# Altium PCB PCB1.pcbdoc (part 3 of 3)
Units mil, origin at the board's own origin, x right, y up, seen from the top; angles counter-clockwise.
Board outline 4706 x 2788 mil, 2 copper layers (Top Layer, Bottom Layer); 153 components, 206 nets, 1095 pads, 513 vias.
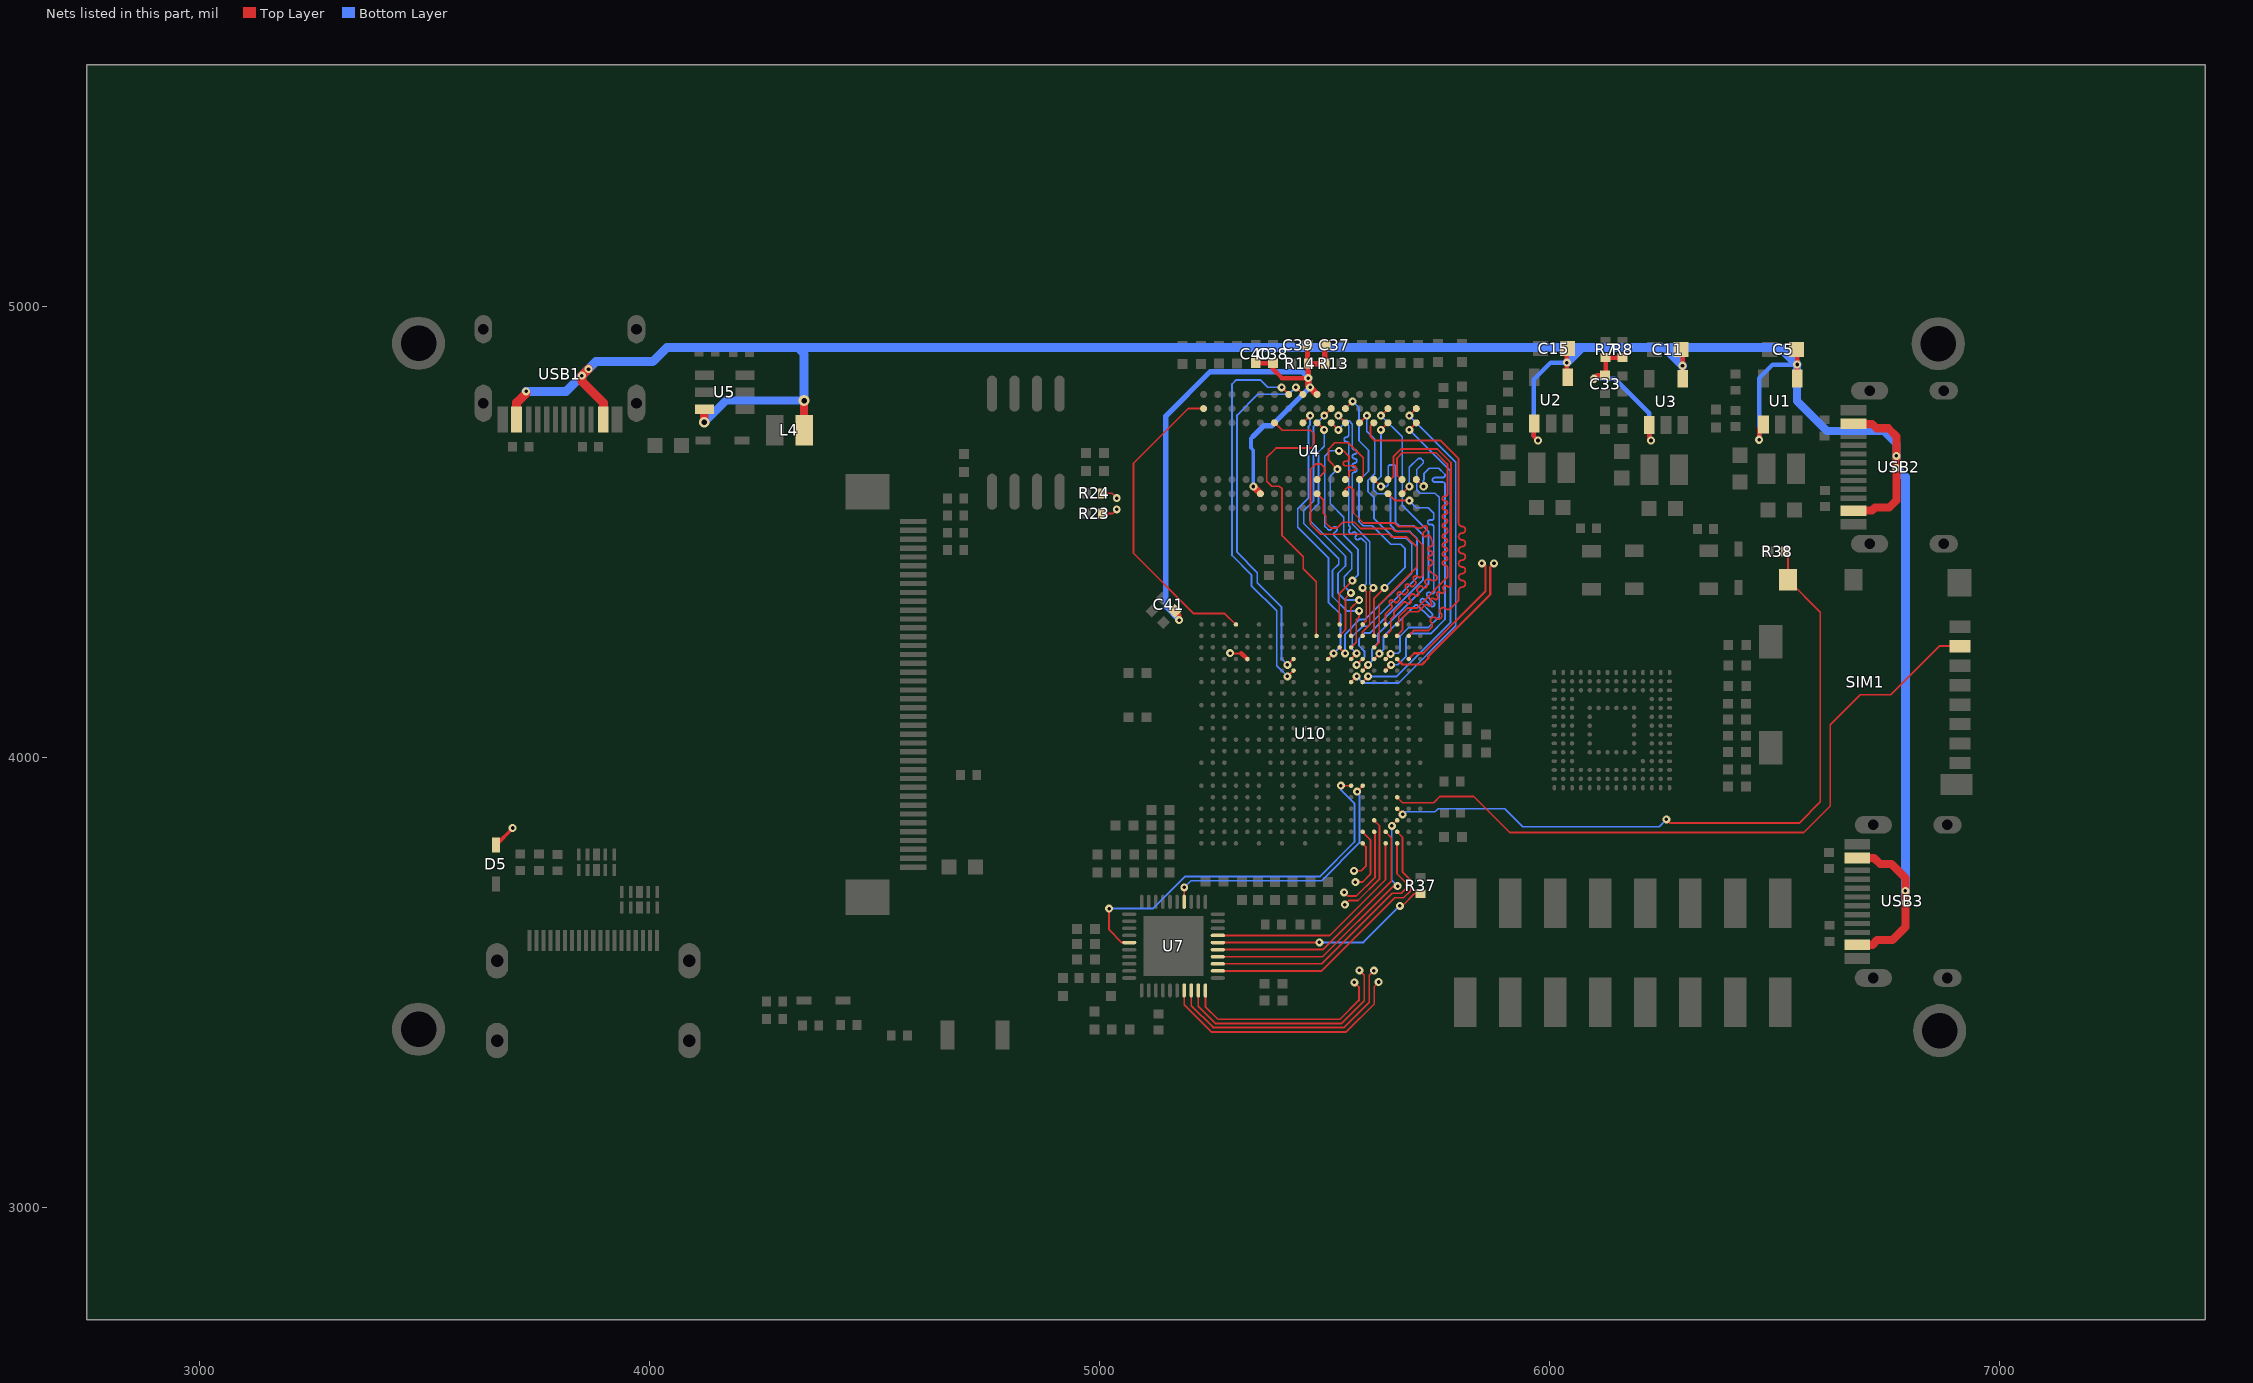
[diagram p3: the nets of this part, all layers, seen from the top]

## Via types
v1: diameter 17.7, hole 7.9, Top Layer to Bottom Layer, 233 vias
v2: diameter 17.72, hole 7.87, Top Layer to Bottom Layer, 140 vias
v3: diameter 17.7, hole 8, Top Layer to Bottom Layer, 88 vias
v4: diameter 18, hole 8, Top Layer to Bottom Layer, 38 vias
v5: diameter 24, hole 15, Top Layer to Bottom Layer, 8 vias
v6: diameter 24, hole 12, Top Layer to Bottom Layer, 6 vias

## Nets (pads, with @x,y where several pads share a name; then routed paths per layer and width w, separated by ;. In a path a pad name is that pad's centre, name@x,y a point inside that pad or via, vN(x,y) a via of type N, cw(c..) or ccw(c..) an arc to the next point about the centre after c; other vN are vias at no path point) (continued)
SDC0_D3: SIM1.2 U10.E3 | length 1571.6
  Top Layer w4: U10.E3@5660.56,3910.73 5672.8,3898.5 5742,3898.5 5756,3912.5 5831,3912.5 5911,3832.5 6564,3832.5 6623,3891.5 6623,4071.5 6690,4138.5 6757,4138.5 6865.2,4246.7 SIM1.2@6911.1,4246.7
SDC0_DET: R38.2 SIM1.12 U10.D3 | length 1585.4
  Top Layer w4: U10.D3@5660.56,3885.14 v1(5673,3872.71) v1@5673,3872.5 ; v1(6259,3861.5) 6267,3853.5 6554,3853.5 6601,3900.5 6601,4322 SIM1.12@6529.2,4393.8 6529.2,4450.31 R38.2@6523,4456.5
  Bottom Layer w4: v1(5673,3872.71) 5678.79,3878.5 5745,3878.5 5752,3885.5 5900,3885.5 5940,3845.5 6243,3845.5 v1(6259,3861.5)
SDC1_CLK: R37.2 U7.16 | length 495.4
  Top Layer w4: U7.16@5262.56,3588.07 5262.99,3588.5 v1(5488,3588.5) ; v1(5667,3669.5) 5670,3672.5 5675,3672.5 5699,3696.5 R37.2@5713,3696.5
  Bottom Layer w4: v1(5488,3588.5) 5586,3588.5 v1(5667,3669.5)
SDC1_CMD: U7.12 U10.B3 | length 645.4
  Top Layer w4: U7.12@5262.56,3525.08 5493.57,3525.08 5656,3687.5 5675,3687.5 5691,3703.5 5691,3726.5 5673,3744.5 5673,3821.53 U10.B3@5660.56,3833.96
SDC1_D0: U7.13 U10.A3 | length 595.4
  Top Layer w4: U7.13@5262.56,3540.83 5493.32,3540.83 5650,3697.5 5670,3697.5 5680,3707.5 5680,3721.5 5660.56,3740.94 U10.A3@5660.56,3808.37
SDC1_D1: U7.14 U10.C3 | length 620.7
  Top Layer w4: U7.14@5262.56,3556.58 5495.07,3556.58 5651,3712.5 5661,3712.5 v1(5662,3713.5) ; v1(5649,3847.5) 5649,3847.99 U10.C3@5660.56,3859.55
  Bottom Layer w4: v1(5649,3847.5) 5649,3726.5 v1(5662,3713.5)
SDC1_D2: U7.17 U10.A4 | length 504.5
  Top Layer w4: U7.17@5262.56,3603.82 5511.31,3603.82 5634.97,3727.47 U10.A4@5634.97,3808.37
SDC1_D3: U7.15 U10.B4 | length 563.3
  Top Layer w4: U7.15@5262.56,3572.33 5495.82,3572.33 5647.76,3724.26 5647.76,3794.26 5648,3794.5 5648,3820.94 U10.B4@5634.97,3833.96
SDQ0: U4.H3 U10.W7 | length 578.3
  Top Layer w4: U4.H3@5483.12,4742.74 v2(5498.87,4727) ; U10.W7@5558.01,4268.98 5558.01,4330.66 v2(5576.24,4348.89)
  Bottom Layer w4: v2(5498.87,4727) 5498.87,4690.52 5486.24,4677.89 5486.24,4562.89 5467.24,4543.89 5467.24,4524.89 5546.24,4445.89 5546.24,4424.89 5529.24,4407.89 5529.24,4364.89 5545.24,4348.89 v2(5576.24,4348.89)
SDQ1: U4.G2 U10.V7 | length 642.4
  Top Layer w4: v2(5499,4758.63) U4.G2@5514.74,4774.37 ; U10.V7@5558.01,4243.39 5570.24,4255.62 5570.24,4304.89 5576.24,4310.89 v2(5576.24,4324.89)
  Bottom Layer w4: v2(5499,4758.63) 5475.24,4734.87 5475.24,4568.89 5453.24,4546.89 5453.24,4518.89 5531.24,4440.89 5531.24,4428.89 5517.24,4414.89 5517.24,4356.89 5549.24,4324.89 v2(5576.24,4324.89)
SDQ2: U4.F7 U10.W8 | length 635.8
  Top Layer w4: v2(5531.7,4680.46) 5541.7,4680.46 5553.7,4668.46 5553.7,4662.2 cw(c5548.7,4662.2) 5548.7,4657.2 5546.18,4657.2 ccw(c5546.18,4652.2) 5541.18,4652.2 ccw(c5546.18,4652.2) 5546.18,4647.2 5564.5,4647.2 cw(c5564.5,4642.2) 5569.5,4642.2 cw(c5564.5,4642.2) 5564.5,4637.2 5558.7,4637.2 ccw(c5558.7,4632.2) 5553.7,4632.2 5553.7,4624.36 U4.F7@5546,4616.65 ; U10.W8@5532.42,4268.98 5546.24,4282.8 5546.24,4352.89 v2(5558.24,4364.89)
  Bottom Layer w4: v2(5531.7,4680.46) 5511.7,4680.46 5499.89,4668.64 5499.89,4513.25 5507.47,4505.67 ccw(c5511.01,4509.2) 5514.54,4505.67 5519.27,4510.39 cw(c5522.8,4506.86) 5526.34,4510.39 cw(c5522.8,4506.86) 5526.34,4503.32 5521.61,4498.6 ccw(c5525.15,4495.06) 5521.61,4491.53 5560.24,4452.89 5560.24,4417.89 5543.24,4400.89 5543.24,4379.89 v2(5558.24,4364.89)
  other v2: 5558.24,4364.89 5558.24,4364.89
SDQ3: U4.E3 U10.V8 | length 706.3
  Top Layer w4: U10.V8@5532.42,4243.39 v2(5545.22,4230.6) ; U4.E3@5577.74,4742.87 v2(5593.49,4758.62)
  Bottom Layer w4: v2(5545.22,4230.6) 5545.22,4272.87 5578.24,4305.89 5590.24,4305.89 5693.24,4408.89 5693.24,4473.89 5680.24,4486.89 5653.24,4486.89 5609.24,4530.89 5609.24,4576.89 5596.24,4589.89 5596.24,4614.89 5611.24,4629.89 5611.24,4705.89 5593.49,4723.65 v2(5593.49,4758.62)
SDQ4: U4.F8 U10.W4 | length 670
  Top Layer w4: U4.F8@5546,4585.15 5546,4594.65 5551.24,4599.89 5558.24,4599.89 5563.87,4594.27 5563.87,4542.27 5586.24,4519.89 5655.24,4519.89 5662.99,4512.15 5695.5,4512.15 cw(c5695.5,4495.14) 5703.5,4510.15 ccw(c5709.78,4521.94) 5719.23,4512.5 cw(c5722.77,4508.96) 5726.3,4512.5 cw(c5722.77,4508.96) 5726.3,4505.42 5719.23,4498.35 ccw(c5722.77,4494.82) 5719.23,4491.28 ccw(c5722.77,4494.82) 5726.3,4491.28 cw(c5729.84,4487.75) 5733.37,4491.28 cw(c5708.75,4472.86) 5739.5,4472.86 cw(c5734.5,4472.86) 5734.5,4467.86 ccw(c5734.5,4462.86) 5729.5,4462.86 ccw(c5734.5,4462.86) 5734.5,4457.86 cw(c5734.5,4452.86) 5739.5,4452.86 cw(c5734.5,4452.86) 5734.5,4447.86 ccw(c5734.5,4442.86) 5729.5,4442.86 ccw(c5734.5,4442.86) 5734.5,4437.86 cw(c5734.5,4432.86) 5739.5,4432.86 cw(c5732.87,4431.86) 5735,4425.5 ccw(c5737.03,4419.44) 5732,4415.5 ccw(c5761.5,4438.64) 5746,4404.5 cw(c5743.4,4398.78) 5748,4394.5 cw(c5741.45,4400.6) 5736,4393.5 ccw(c5730.48,4386.31) 5724.07,4392.72 ccw(c5727.6,4389.18) 5724.07,4385.65 5725.5,4384.22 cw(c5721.96,4380.69) 5725.5,4377.15 cw(c5721.96,4380.69) 5718.43,4377.15 5717,4378.58 ccw(c5713.46,4375.04) 5709.93,4378.58 5706.39,4375.04 ccw(c5709.93,4371.51) 5706.39,4367.97 5707.82,4366.54 cw(c5704.28,4363.01) 5707.82,4359.47 cw(c5704.28,4363.01) 5700.75,4359.47 5699.32,4360.9 ccw(c5695.78,4357.36) 5692.25,4360.9 5688.71,4357.36 ccw(c5692.25,4353.83) 5688.71,4350.29 5690.14,4348.87 cw(c5686.61,4345.33) 5690.14,4341.79 cw(c5686.61,4345.33) 5683.07,4341.79 5681.64,4343.22 ccw(c5678.11,4339.69) 5674.57,4343.22 5654.24,4322.89 5654.24,4313.89 5646.69,4306.34 5646.69,4280.89 U10.W4@5634.78,4268.98
SDQ5: U4.H8 U10.Y4 | length 604.4
  Top Layer w4: U4.H8@5483,4585.15 5497.5,4570.65 5497.5,4541.15 5502.5,4536.15 5502.5,4520.15 5513.5,4509.15 5527.5,4509.15 5540.24,4521.89 5566.24,4521.89 5580.24,4507.89 5649.24,4507.89 5655.24,4501.89 5687.24,4501.89 5717.24,4471.89 5717.24,4405.9 cw(c5710.41,4405.9) 5711.5,4399.15 cw(c5710.67,4404.32) 5706.5,4401.15 ccw(c5702.52,4396.44) 5698.15,4400.81 ccw(c5701.69,4397.27) 5698.15,4393.73 5701.08,4390.81 cw(c5697.55,4387.27) 5701.08,4383.73 5697.55,4380.2 cw(c5694.01,4383.73) 5690.48,4380.2 5687.55,4383.13 ccw(c5684.01,4379.59) 5680.48,4383.13 ccw(c5684.01,4379.59) 5680.48,4376.06 5683.4,4373.13 cw(c5679.87,4369.59) 5683.4,4366.06 5679.87,4362.52 cw(c5676.33,4366.06) 5672.8,4362.52 5669.87,4365.45 ccw(c5666.33,4361.91) 5662.8,4365.45 ccw(c5666.33,4361.91) 5662.8,4358.38 5665.73,4355.45 cw(c5662.19,4351.91) 5665.73,4348.38 5662.19,4344.84 cw(c5658.66,4348.38) 5655.12,4344.84 5652.19,4347.77 ccw(c5648.66,4344.24) 5645.12,4347.77 ccw(c5648.66,4344.24) 5645.12,4340.7 5648.05,4337.77 cw(c5644.51,4334.24) 5648.05,4330.7 5634.78,4317.44 U10.Y4@5634.78,4294.57
SDQ6: U4.H7 U10.V5 | length 713.7
  Top Layer w4: U4.H7@5483,4616.65 5499.24,4632.88 5499.24,4643.89 5492.24,4650.89 5480.24,4650.89 5468.4,4639.05 5468.4,4517.74 5491.24,4494.89 5643.24,4494.89 5649.24,4488.89 5682.24,4488.89 5704.24,4466.89 5704.24,4421.89 5621.24,4338.89 5621.24,4255.44 U10.V5@5609.19,4243.39
SDQ7: U4.F2 U10.W5 | length 662.7
  Top Layer w4: U4.F2@5546.24,4774.37 v2(5561.99,4790.12) ; U10.W5@5609.19,4268.98 5609.19,4351.84 v2(5633.24,4375.89)
  Bottom Layer w4: v2(5561.99,4790.12) 5576.24,4775.87 5576.24,4702.89 5597.24,4681.89 5597.24,4634.89 5576.24,4613.89 5576.24,4522.89 5585.24,4513.89 5605.24,4513.89 5646.24,4472.89 5669.24,4472.89 5678.24,4463.89 5678.24,4420.89 v2(5633.24,4375.89)
SDQ8: U4.B8 U10.U4 | length 677
  Top Layer w4: U10.U4@5634.78,4217.8 5646.13,4229.15 v2(5646.5,4229.15) ; U4.B8@5672,4585.15 v2(5687.97,4601.14)
  Bottom Layer w4: v2(5646.5,4229.15) 5647.95,4230.6 5662.95,4230.6 5667.24,4234.89 5667.24,4268.89 5686.24,4287.89 5730.24,4287.89 5754.24,4311.89 5754.24,4576.89 5744.93,4586.21 5711.93,4586.21 5704.24,4593.89 5704.24,4638.89 5718.7,4653.35 5718.7,4658.43 5713.68,4663.46 5707.81,4663.46 5687.97,4643.62 v2(5687.97,4601.14)
SDQ9: U4.C3 U10.U7 | length 683.9
  Top Layer w4: U10.U7@5558.01,4217.8 v2(5570.81,4230.6) ; v2(5624.99,4727.13) U4.C3@5640.73,4742.87
  Bottom Layer w4: v2(5570.81,4230.6) 5561.24,4240.16 5561.24,4267.89 5584.24,4290.89 5596.24,4290.89 5705.24,4399.89 5705.24,4484.89 5689.24,4500.89 5660.24,4500.89 5646.24,4514.89 5646.24,4576.89 5638.24,4584.89 5617.24,4584.89 5608.24,4593.89 5608.24,4606.89 5624.99,4623.64 v2(5624.99,4727.13)
SDQ10: U4.C8 U10.U5 | length 660.2
  Top Layer w4: U10.U5@5609.19,4217.8 v2(5621.19,4229.8) ; U4.C8@5640.73,4585.39 5656.23,4569.89 v2@5687.24,4569.89
  Bottom Layer w4: v2(5621.19,4229.8) 5630.5,4239.11 5630.5,4267.15 5699.82,4336.47 cw(c5703.35,4332.94) 5706.89,4336.47 5730.82,4312.54 ccw(c5734.35,4316.08) 5737.89,4312.54 ccw(c5734.35,4316.08) 5737.89,4319.61 5713.96,4343.54 cw(c5717.5,4347.08) 5713.96,4350.61 cw(c5717.5,4347.08) 5721.03,4350.61 5735.64,4336.01 ccw(c5739.17,4339.54) 5742.71,4336.01 ccw(c5739.17,4339.54) 5742.71,4343.08 5728.1,4357.68 cw(c5731.64,4361.22) 5728.1,4364.76 cw(c5731.64,4361.22) 5735.17,4364.76 5735.64,4364.29 ccw(c5739.17,4367.83) 5742.71,4364.29 ccw(c5739.17,4367.83) 5742.71,4371.36 5742.24,4371.83 5742.24,4511.49 ccw(c5737.24,4511.49) 5737.24,4516.49 5733.67,4516.49 cw(c5733.67,4521.49) 5728.67,4521.49 cw(c5733.67,4521.49) 5733.67,4526.49 5737.24,4526.49 ccw(c5737.24,4531.49) 5742.24,4531.49 5742.24,4541.89 5730.24,4553.89 5703.72,4553.89 v2(5687.97,4569.65)
  other v2: 5621.19,4229.8 5621.19,4229.8
SDQ11: U4.C2 U10.T6 | length 693
  Top Layer w4: U10.T6@5583.6,4192.21 v2(5596.4,4205.01) ; v2(5624.99,4758.63) U4.C2@5640.73,4774.37
  Bottom Layer w4: v2(5596.4,4205.01) 5605.24,4213.86 5605.24,4239.89 5618.24,4252.89 5618.24,4272.89 5730.24,4384.89 5730.24,4501.89 5672.24,4559.89 5672.24,4711.37 v2(5624.99,4758.63)
SDQ12: U4.D7 U10.U6 | length 682
  Top Layer w4: v2(5570.81,4205.01) U10.U6@5583.6,4217.8 ; U4.D7@5609,4616.65 v2(5624.98,4601.15)
  Bottom Layer w4: v2(5570.81,4205.01) 5588.24,4222.44 5588.24,4235.53 5576.24,4247.53 5576.24,4262.89 5589.24,4275.89 5601.24,4275.89 5718.24,4392.89 5718.24,4493.89 5698.24,4513.89 5665.24,4513.89 5657.24,4521.89 5657.24,4646.55 5654.9,4648.89 5643.59,4648.89 5641.24,4646.55 5641.24,4604.89 5637.5,4601.15 v2(5624.98,4601.15)
SDQ13: U4.A2 U10.R7 | length 829.3
  Top Layer w4: U10.R7@5558.01,4166.62 v2(5570.81,4179.42) ; v2(5687.98,4758.63) U4.A2@5703.72,4774.37
  Bottom Layer w4: v2(5570.81,4179.42) 5585.73,4164.5 5663.85,4164.5 5791.24,4291.89 5791.24,4655.36 v2(5687.98,4758.63)
SDQ14: U4.A7 U10.T4 | length 681.3
  Top Layer w4: U10.T4@5634.78,4192.21 v2(5647.58,4205.01) ; U4.A7@5703.5,4616.65 v2(5719.47,4601.15)
  Bottom Layer w4: v2(5647.58,4205.01) 5662.36,4205.01 5680.24,4222.89 5680.24,4263.89 5691.24,4274.89 5736.24,4274.89 5767.24,4305.89 5767.24,4605.88 ccw(c5762.24,4605.88) 5762.24,4610.88 5744.5,4610.88 cw(c5744.5,4615.88) 5739.5,4615.88 cw(c5744.5,4615.88) 5744.5,4620.88 5762.24,4620.88 ccw(c5762.24,4625.88) 5767.24,4625.88 5767.24,4627.89 5753.24,4641.89 5732.24,4641.89 5720.24,4629.89 v2(5719.47,4601.15)
  other v2: 5720.24,4601.89
SDQ15: U4.A3 U10.R6 | length 738.7
  Top Layer w4: U10.R6@5583.6,4166.62 v2(5596.4,4179.42) ; v2(5687.98,4727.13) U4.A3@5703.72,4742.87
  Bottom Layer w4: v2(5596.4,4179.42) 5659.77,4179.42 5779.24,4298.89 5779.24,4635.86 v2(5687.98,4727.13)
SDQM0: U4.E7 U10.Y8 | length 596.3
  Top Layer w4: v2(5528.24,4639.89) 5508.7,4659.43 5508.7,4684.46 5522.7,4698.46 5552.7,4698.46 5585.7,4665.46 5585.7,4624.86 U4.E7@5577.5,4616.65 ; U10.Y8@5532.42,4294.57 5532.42,4363.07 v2(5561.24,4391.89)
  Bottom Layer w4: v2(5528.24,4639.89) 5512.24,4623.89 5512.24,4563.41 5542.5,4533.15 5542.5,4492.64 5574.24,4460.89 5574.24,4404.89 v2(5561.24,4391.89)
SDQM1: U4.D3 U10.W2 | length 829.4
  Top Layer w4: U4.D3@5609,4742.65 5601.5,4735.15 5601.5,4713.15 5611.5,4703.15 5757.5,4703.15 5797.5,4663.15 5797.5,4520.05 ccw(c5805,4520.05) 5805,4512.55 cw(c5805,4505.05) 5812.5,4505.05 cw(c5805,4505.05) 5805,4497.55 ccw(c5805,4490.05) 5797.5,4490.05 ccw(c5805,4490.05) 5805,4482.55 cw(c5805,4475.05) 5812.5,4475.05 cw(c5805,4475.05) 5805,4467.55 ccw(c5805,4460.05) 5797.5,4460.05 ccw(c5805,4460.05) 5805,4452.55 cw(c5805,4445.05) 5812.5,4445.05 cw(c5805,4445.05) 5805,4437.55 ccw(c5805,4430.05) 5797.5,4430.05 ccw(c5805,4430.05) 5805,4422.55 cw(c5805,4415.05) 5812.5,4415.05 cw(c5805,4415.05) 5805,4407.55 ccw(c5805,4400.05) 5797.5,4400.05 ccw(c5805,4400.05) 5805,4392.55 cw(c5805,4385.05) 5812.5,4385.05 cw(c5805,4385.05) 5805,4377.55 ccw(c5805,4370.05) 5797.5,4370.05 5797.5,4348.15 5779.29,4329.94 cw(c5773.99,4335.25) 5768.69,4329.94 ccw(c5763.38,4324.64) 5758.08,4329.94 ccw(c5763.38,4324.64) 5758.08,4319.34 cw(c5752.78,4314.03) 5758.08,4308.73 cw(c5752.78,4314.03) 5747.47,4308.73 ccw(c5742.17,4303.43) 5736.87,4308.73 ccw(c5742.17,4303.43) 5736.87,4298.12 cw(c5731.56,4292.82) 5736.87,4287.52 5730.5,4281.15 5697.5,4281.15 U10.W2@5685.15,4268.8
SDQS0N: U4.G3 U10.Y6 | length 553.7
  Top Layer w4: U4.G3@5514.74,4742.87 v2(5530.49,4727.13) ; U10.Y6@5583.6,4294.57 5592.24,4303.21 5592.24,4366.99 5584.4,4374.83 v2(5584.4,4376.19)
  Bottom Layer w4: v2(5530.49,4727.13) 5530.49,4727.81 5541.56,4738.87 5550.9,4738.87 5553.24,4736.53 5553.24,4715.76 cw(c5548.24,4715.76) 5548.24,4710.76 ccw(c5548.24,4705.76) 5543.24,4705.76 ccw(c5548.24,4705.76) 5548.24,4700.76 cw(c5548.24,4695.76) 5553.24,4695.76 5553.24,4514.58 5555.2,4512.63 cw(c5551.66,4509.09) 5555.2,4505.56 ccw(c5558.73,4502.02) 5555.2,4498.49 ccw(c5558.73,4502.02) 5562.27,4498.49 cw(c5565.8,4494.95) 5569.34,4498.49 cw(c5565.8,4494.95) 5569.34,4491.42 ccw(c5572.87,4487.88) 5569.34,4484.35 ccw(c5572.87,4487.88) 5576.41,4484.35 cw(c5579.94,4480.81) 5583.48,4484.35 5592.24,4475.58 5592.24,4385.39 5584.4,4377.55 v2(5584.4,4376.19)
  other v2: 5530.49,4727.13
SDQS0P: U4.F3 U10.W6 | length 597.2
  Top Layer w4: v2(5530.5,4758.62) U4.F3@5546.24,4742.87 ; U10.W6@5583.73,4269.07 5583.73,4277.83 5600.24,4294.34 5600.24,4366.99 v2(5608.09,4376.19) v2@5608.09,4374.83
  Bottom Layer w4: v2@5530.5,4757.93 v2(5530.5,4758.62) 5541.56,4746.87 5554.21,4746.87 5561.24,4739.85 5561.24,4688.07 ccw(c5566.24,4688.07) 5566.24,4683.07 cw(c5566.24,4678.07) 5571.24,4678.07 cw(c5566.24,4678.07) 5566.24,4673.07 ccw(c5566.24,4668.07) 5561.24,4668.07 ccw(c5566.24,4668.07) 5566.24,4663.07 cw(c5566.24,4658.07) 5571.24,4658.07 cw(c5566.24,4658.07) 5566.24,4653.07 ccw(c5566.24,4648.07) 5561.24,4648.07 ccw(c5566.24,4648.07) 5566.24,4643.07 cw(c5566.24,4638.07) 5571.24,4638.07 cw(c5566.24,4638.07) 5566.24,4633.07 ccw(c5566.24,4628.07) 5561.24,4628.07 5561.24,4517.89 5600.24,4478.89 5600.24,4385.39 5608.09,4377.55 v2(5608.09,4376.19)
  other v2: 5608.09,4376.19
SDQS1N: U4.B7 U10.Y3 | length 703.9
  Top Layer w4: U10.Y3@5659.56,4294.39 5664.5,4299.33 5664.5,4312.47 5683.19,4331.15 5704.5,4331.15 5772.5,4399.15 5772.5,4421.02 ccw(c5767.5,4421.02) 5767.5,4426.02 5766.5,4426.02 cw(c5766.5,4431.02) 5761.5,4431.02 cw(c5766.5,4431.02) 5766.5,4436.02 5767.5,4436.02 ccw(c5767.5,4441.02) 5772.5,4441.02 ccw(c5767.5,4441.02) 5767.5,4446.02 5766.5,4446.02 cw(c5766.5,4451.02) 5761.5,4451.02 cw(c5766.5,4451.02) 5766.5,4456.02 5767.5,4456.02 ccw(c5767.5,4461.02) 5772.5,4461.02 ccw(c5767.5,4461.02) 5767.5,4466.02 5766.5,4466.02 cw(c5766.5,4471.02) 5761.5,4471.02 cw(c5766.5,4471.02) 5766.5,4476.02 5767.5,4476.02 ccw(c5767.5,4481.02) 5772.5,4481.02 ccw(c5767.5,4481.02) 5767.5,4486.02 5766.5,4486.02 cw(c5766.5,4491.02) 5761.5,4491.02 cw(c5766.5,4491.02) 5766.5,4496.02 5767.5,4496.02 ccw(c5767.5,4501.02) 5772.5,4501.02 5772.5,4504.38 ccw(c5767.5,4504.38) 5767.5,4509.38 5766.5,4509.38 cw(c5766.5,4514.38) 5761.5,4514.38 cw(c5766.5,4514.38) 5766.5,4519.38 5767.5,4519.38 ccw(c5767.5,4524.38) 5772.5,4524.38 ccw(c5767.5,4524.38) 5767.5,4529.38 5766.5,4529.38 cw(c5766.5,4534.38) 5761.5,4534.38 cw(c5766.5,4534.38) 5766.5,4539.38 5767.5,4539.38 ccw(c5767.5,4544.38) 5772.5,4544.38 ccw(c5767.5,4544.38) 5767.5,4549.38 5766.5,4549.38 cw(c5766.5,4554.38) 5761.5,4554.38 cw(c5766.5,4554.38) 5766.5,4559.38 5767.5,4559.38 ccw(c5767.5,4564.38) 5772.5,4564.38 ccw(c5767.5,4564.38) 5767.5,4569.38 5766.5,4569.38 cw(c5766.5,4574.38) 5761.5,4574.38 cw(c5766.5,4574.38) 5766.5,4579.38 5767.5,4579.38 ccw(c5767.5,4584.38) 5772.5,4584.38 5772.5,4650.84 5747.19,4676.15 5672.5,4676.15 5660.5,4664.15 5660.5,4626.15 5670,4616.65 U4.B7@5672,4616.65
SDQS1P: U4.C7 U10.W3 | length 698.1
  Top Layer w4: U4.C7@5640.5,4616.65 5646,4616.65 5652.5,4623.15 5652.5,4667.47 5669.19,4684.15 5750.5,4684.15 5780.5,4654.15 5780.5,4384.15 cw(c5773.56,4384.59) 5778.48,4379.68 cw(c5774.94,4383.21) 5771.41,4379.68 ccw(c5767.87,4376.14) 5764.34,4379.68 ccw(c5767.87,4376.14) 5764.34,4372.6 cw(c5760.8,4369.07) 5764.34,4365.53 cw(c5760.8,4369.07) 5757.27,4365.53 ccw(c5753.73,4362) 5750.19,4365.53 ccw(c5753.73,4362) 5750.19,4358.46 cw(c5746.66,4354.93) 5750.19,4351.39 cw(c5746.66,4354.93) 5743.12,4351.39 ccw(c5739.59,4347.86) 5736.05,4351.39 ccw(c5739.59,4347.86) 5736.05,4344.32 cw(c5732.52,4340.79) 5736.05,4337.25 cw(c5732.52,4340.79) 5728.98,4337.25 ccw(c5725.45,4333.71) 5721.91,4337.25 5707.81,4323.15 5686.5,4323.15 5672.5,4309.15 5672.5,4281.74 U10.W3@5659.56,4268.8
SODT0: U4.K1 U10.T12 | length 861.5
  Top Layer w4: v2(5404.52,4821.61) U4.K1@5420.26,4805.86 ; v2(5417.26,4179.42) U10.T12@5430.05,4192.21
  Bottom Layer w4: v2(5404.52,4821.61) 5373.04,4821.61 5356.76,4837.89 5303.24,4837.89 5294.24,4828.89 5294.24,4447.89 5337.24,4404.89 5337.24,4380.89 5393.24,4324.89 5393.24,4203.43 v2(5417.26,4179.42)
SODT1: U4.J1 U10.U12 | length 798
  Top Layer w4: v2(5417.26,4205.01) U10.U12@5430.05,4217.8 ; v2(5436.01,4821.61) U4.J1@5451.75,4805.86
  Bottom Layer w4: v2(5417.26,4205.01) 5404.24,4218.02 5404.24,4332.89 5350.24,4386.89 5350.24,4409.89 5305.24,4454.89 5305.24,4759.89 5351.24,4805.89 5420.29,4805.89 v2(5436.01,4821.61)
SRAS: U4.J3 U10.U9 | length 625.5
  Top Layer w4: U4.J3@5451.75,4742.87 v2(5467.5,4758.62) ; U10.U9@5506.83,4217.8 v2(5519.63,4230.6)
  Bottom Layer w4: v2(5467.5,4758.62) 5467.5,4738.45 5464.24,4735.19 5464.24,4575.89 5440.24,4551.89 5440.24,4510.89 5508.24,4442.89 5508.24,4343.89 5535.24,4316.89 5535.24,4246.21 v2(5519.63,4230.6)
SRST: U4.T2 U10.Y17 | length 698.8
  Top Layer w4: U4.T2@5231.28,4774.37 5196.72,4774.37 5075.24,4652.89 5075.24,4452.89 5209.24,4318.89 5277.78,4318.89 U10.Y17@5302.1,4294.57
SVREF: C37.1 C38.2 C39.2 C40.2 C41.2 R13.1 R14.2 U4.H1 U4.M8 U10.U16 | length 1851.8
  Top Layer w4.5: v2@5288.81,4230.6 5314.9,4230.6
  Top Layer w10: C41.2@5167.41,4324.78 5176.7,4315.49 v1(5176.7,4304.46) ; 5314.9,4230.6 U10.U16@5327.69,4217.8 ; C40.2@5346.7,4875.45 C38.2@5384.7,4875.45 5384.7,4862.46 5405.08,4842.08 v4(5463.5,4842.08)
  Top Layer w12: v2@5288.56,4230.6 v2@5289.02,4231.06 ; C39.2@5461.71,4915.46 5461.7,4875.96 R14.2@5463.5,4874.16 ; v4(5463.5,4842.08) R14.2@5463.5,4874.16 ; C37.1@5497.7,4915.46 5500.5,4912.66 R13.1@5500.5,4874.15 R14.2@5463.5,4874.16
  Top Layer w15: v2(5341.52,4601.14) U4.M8@5357.26,4585.39 ; v4(5463.5,4842.08) 5463.5,4825.62 U4.H1@5483.25,4805.86
  Mid-Layer 2 w13: v1(5176.7,4304.46) 5211.75,4339.5 5287,4339.5 5333.76,4292.74 5333.76,4254.26 5310.56,4231.06 v2(5289.7,4231.06)
  Bottom Layer w8: 5340.7,4712.46 5336.24,4708 5336.24,4686.92 5341.52,4681.65 v2(5341.52,4601.14)
  Bottom Layer w12: v1(5176.7,4304.46) 5147,4334.16 5147,4757.75 5245.7,4856.46 5449.12,4856.46 v4(5463.5,4842.08) ; v2@5286.85,4230.6 5287.7,4231.46 v2@5289.3,4231.46 ; 5340.7,4712.46 5364.7,4736.46 5382.35,4736.46 v2(5467.51,4821.61)
  Bottom Layer w15: v4(5463.5,4842.08) 5463.5,4825.62 v2(5467.51,4821.61)
SWE: U4.L3 U10.W10 | length 691.1
  Top Layer w4: U4.L3@5388.76,4742.87 5405.6,4726.03 5468.37,4726.03 5476.24,4718.16 5476.24,4693.89 5468.81,4686.46 5391.81,4686.46 5371.14,4665.79 5371.14,4613 5382.24,4601.89 5399.24,4601.89 5405.24,4595.89 5405.24,4491.89 5452.24,4444.89 5452.24,4418.89 5481.24,4389.89 U10.W10@5481.24,4268.98
UART0_RX: R23.1 U10.U3 | length 1997.4
  Top Layer w4: R23.1@5006.5,4541 5028.5,4541 v1(5038,4550.5)
  Top Layer w5: U10.U3@5660.56,4217.82 5672.89,4205.5 5716,4205.5 5730,4219.5 5730,4223.5 5868,4361.5 5868,4422.5 v3(5876,4430.5)
  Mid-Layer 2 w4: v1(5038,4550.5) 5023,4550.5 4999,4574.5 4999,4766.5 5148,4915.5 5783,4915.5 5867,4831.5 5867,4439.5 v3(5876,4430.5)
UART0_TX: R24.1 U10.U2 | length 1876
  Top Layer w4: R24.1@5006.5,4586 5027.5,4586 v1(5038,4575.5)
  Top Layer w5: U10.U2@5686.15,4217.82 5698.83,4230.5 5719,4230.5 5857,4368.5 5857,4425.5
  Mid-Layer 2 w4: v1(5038,4575.5) 5037,4574.5 5021,4574.5 5010,4585.5 5010,4761.5 5156,4907.5 5777,4907.5 5857,4827.5 5857,4438.5 v3(5849,4430.5)
UART1_CTS: U7.7 U10.B6 | length 949.9
  Top Layer w4: U7.7@5187.78,3481.8 5187.78,3449.72 5248,3389.5 5548,3389.5 5610,3451.5 5610,3490.5 v1(5620,3500.5) ; v1(5568,3722.5) 5584,3722.5 5602,3740.5 5602,3815.76 U10.B6@5583.79,3833.96
  Mid-Layer 2 w4: v1(5568,3722.5) 5568,3715.5 5600,3683.5 5600,3556.5 5627,3529.5 5627,3507.5 v1(5620,3500.5)
UART1_RTS: U7.8 U10.A6 | length 889.7
  Top Layer w4: U7.8@5203.53,3481.8 5203.53,3447.97 5252,3399.5 5543,3399.5 5599,3455.5 5599,3515.5 v1(5609,3525.5) ; v1(5565,3747.5) 5581,3747.5 5592,3758.5 5592,3800.17 U10.A6@5583.79,3808.37
  Mid-Layer 2 w4: v1(5565,3747.5) 5557,3747.5 5549,3739.5 5549,3717.5 5589,3677.5 5589,3545.5 v1(5609,3525.5)
UART1_RX: U7.10 U10.C5 | length 873.8
  Top Layer w4: U7.10@5235.03,3481.8 5235.03,3445.47 5263,3417.5 5534,3417.5 5576,3459.5 5576,3489.5 v1(5566,3499.5) ; v1(5545,3672.5) 5554,3681.5 5574,3681.5 5622,3729.5 5622,3846.94 U10.C5@5609.38,3859.55
  Mid-Layer 2 w4: v1(5545,3672.5) 5564,3653.5 5564,3539.5 5557,3532.5 5557,3508.5 v1(5566,3499.5)
UART1_TX: U7.9 U10.B5 | length 891.5
  Top Layer w4: U7.9@5219.28,3481.8 5219.28,3446.22 5257,3408.5 5538,3408.5 5588,3458.5 5588,3515.5 v1(5577,3526.5) ; v1(5543,3699.5) 5551,3691.5 5570,3691.5 5612,3733.5 5612,3831.35 U10.B5@5609.38,3833.96
  Mid-Layer 2 w4: v1(5543,3699.5) 5577,3665.5 v1(5577,3526.5)
VBUS: C5.2 C11.2 C15.2 D5.2 L4.1 U1.1 U1.4 U2.1 U2.4 U3.4 U5.6 USB1.A4B9 USB1.B4A9 USB2.A4B9 USB2.B4A9 USB3.A4B9 USB3.B4A9 | length 7515.4
  Top Layer w8: D5.2@3659,3804.7 v1@3696.4,3842.1 ; v1@3693.9,3839.6 3693.9,3840.4 v1(3696,3842.5)
  Top Layer w10: U2.1@5965.47,4741.21 5964.87,4740.61 5964.87,4712.4 v4(5973.87,4703.4) ; U2.4@6037.87,4841.18 v4(6037.87,4876.46) 6037.87,4906.4 C15.2@6038.87,4907.4 ; C11.2@6291.4,4905.4 6295.67,4901.13 v4@6295.67,4868.6 ; v4(6294.87,4869.4) v4@6295.67,4868.6 ; U3.4@6295.67,4840.4 v4@6295.67,4868.6 ; v4(6465.14,4705.11) 6465.14,4729.32 U1.1@6474.74,4738.92 ; C5.2@6547.67,4905.11 6549.54,4903.24 v4(6549.54,4872.18) U1.4@6549.54,4841.29
  Top Layer w18: U5.6@4121.76,4773.1 v6(4121.76,4743.74) v6@4122,4743.5 ; L4.1@4343.6,4726.5 v6(4343.6,4792.1) v6@4344,4792.5 ; USB2.A4B9@6674.55,4547.46 6715.45,4547.46 6722.49,4554.5 6754,4554.5 6770,4570.5 v1(6770,4642.26) v1(6770,4669.28) 6770,4712.5 6752,4730.5 6725.35,4730.5 6715.48,4740.37 USB2.B4A9@6674.55,4740.37 ; USB3.A4B9@6680.17,3583.04 USB3.A4B9@6682.71,3583.04 6716.54,3583.04 6727,3593.5 6761,3593.5 6790,3622.5 v1(6790,3677.32) v1(6790,3702.95) 6790,3731.5 6759,3762.5 6734,3762.5 6720.55,3775.95 USB3.B4A9@6682.71,3775.95
  Top Layer w20: USB1.B4A9@3704.86,4751.52 3704.86,4787.36 v3@3726,4808.5 ; v1(3864.49,4861.99) v1(3850,4847.5) 3850,4834.5 3897.77,4786.73 USB1.A4B9@3897.77,4751.52 ; USB3.A4B9@6682.71,3583.04 USB3.A4B9@6684.17,3584.5
  Mid-Layer 1 w10: v1(3696,3842.5) 3712,3858.5 3712,4798.5 v3(3726,4812.5)
  Bottom Layer w10: v4(5973.87,4703.4) 5964.87,4712.4 5964.87,4839.4 6001.93,4876.46 v4(6037.87,4876.46) ; v4(6465.14,4705.11) 6465.14,4842.11 6495.21,4872.18 v4(6549.54,4872.18)
  Bottom Layer w18: v6(4121.76,4743.74) 4170.12,4792.1 v6(4343.6,4792.1) ; v4(6549.54,4872.18) 6549.54,4790.96 6616,4724.5 6742,4724.5 6770,4696.5 v1(6770,4669.28) v1(6770,4642.26)
  Bottom Layer w20: v3(3726,4812.5) 3815,4812.5 v1(3850,4847.5) v1(3864.49,4861.99) 3881,4878.5 4007,4878.5 4039,4910.5 4328.9,4910.5 ; v6(4343.6,4792.1) 4343.6,4895.8 4328.9,4910.5 ; v4(6037.87,4876.46) 6071.91,4910.5 ; v4(6294.87,4869.4) 6253.77,4910.5 ; v4(6549.54,4872.18) 6511.22,4910.5 6253.77,4910.5 ; v1(6770,4642.26) 6790,4622.26 v1(6790,3702.95) v1(6790,3677.32) ; 4328.9,4910.5 6071.91,4910.5 ; 6071.91,4910.5 6253.77,4910.5
VCPU_EN: C33.2 R7.1 R8.2 U3.1 | length 358.4
  Top Layer w10: v4(6098,4840.5) 6105.9,4848.4 C33.2@6122.87,4848.4 6123.87,4849.4 R7.1@6123.87,4887.4 R8.2@6161.87,4887.4 ; U3.1@6220.87,4738.03 6220.87,4707.4 v4(6224.87,4703.4)
  Bottom Layer w10: v4(6098,4840.5) 6144,4840.5 6220.87,4763.63 6220.87,4707.4 v4(6224.87,4703.4)
WL_REG_ON: U7.24 U10.F6 | length 595.8
  Top Layer w4: U7.24@5187.78,3678.6 5187.78,3710.28 v1(5188,3710.5) ; v1(5572,3923.5) 5583.79,3935.29 U10.F6@5583.79,3936.32
  Bottom Layer w4: v1(5188,3710.5) 5203,3725.5 5493,3725.5 5577,3809.5 5577,3918.5 v1(5572,3923.5)
WL_WAKE_AP: U7.35 U10.F7 | length 869.5
  Top Layer w4: v1(5021,3663.5) 5021,3616.5 5049.43,3588.07 U7.35@5065.76,3588.07 ; v1(5536,3936.5) 5558.02,3936.5 U10.F7@5558.2,3936.32
  Bottom Layer w4: v1(5021,3663.5) 5118,3663.5 5189,3734.5 5489,3734.5 5566,3811.5 5566,3897.5 5536,3927.5 v1(5536,3936.5)
"": 
pads on no net: CN1.14 FEL.1 FEL.4 LCD1.7 LCD1.8 RESET.1 RESET.4 U6.4 U7.27 U7.29 U7.31 U7.32 U7.33 U7.34 U7.39 U9.A1 U9.A2 U9.A7 U9.A8 U9.A9 U9.A10 U9.A11 U9.A12 U9.A13 U9.A14 U9.B1 U9.B3 U9.B4 U9.B5 U9.B6 U9.B7 U9.B8 U9.B9 U9.B10 U9.B11 U9.B12 U9.B13 U9.B14 U9.C1 U9.C3 U9.C5 U9.C7 U9.C8 U9.C9 U9.C10 U9.C11 U9.C12 U9.C13 U9.C14 U9.D1 U9.D2 U9.D3 U9.D4 U9.D12 U9.D13 U9.D14 U9.E1 U9.E2 U9.E3 U9.E5 U9.E8 U9.E9 U9.E10 U9.E12 U9.E13 U9.E14 U9.F1 U9.F2 U9.F3 U9.F10 U9.F12 U9.F13 U9.F14 U9.G1 U9.G2 U9.G3 U9.G10 U9.G12 U9.G13 U9.G14 U9.H1 U9.H2 U9.H3 U9.H5 U9.H12 U9.H13 U9.H14 U9.J1 U9.J2 U9.J3 U9.J12 U9.J13 U9.J14 U9.K1 U9.K2 U9.K3 U9.K6 U9.K7 U9.K10 U9.K12 U9.K13 U9.K14 U9.L1 U9.L2 U9.L3 U9.L12 U9.L13 U9.L14 U9.M1 U9.M2 U9.M3 U9.M7 U9.M8 U9.M9 U9.M10 U9.M11 U9.M12 U9.M13 U9.M14 U9.N1 U9.N3 U9.N6 U9.N7 U9.N8 U9.N9 U9.N10 U9.N11 U9.N12 U9.N13 U9.N14 U9.P1 U9.P2 U9.P7 U9.P8 U9.P9 U9.P10 U9.P11 U9.P12 U9.P13 U9.P14 U10.A11 U10.A13 U10.A17 U10.B9 U10.B11 U10.B12 U10.B13 U10.B14 U10.B15 U10.B16 U10.B17 U10.C9 U10.C11 U10.C12 U10.C13 U10.C14 U10.C15 U10.C16 U10.C17 U10.D7 U10.D9 U10.D13 U10.D15 U10.D16 U10.D17 U10.D19 U10.D20 U10.E7 U10.E10 U10.E13 U10.E15 U10.E16 U10.E17 U10.E18 U10.E19 U10.F2 U10.F10 U10.F13 U10.F15 U10.F16 U10.F17 U10.J15 U10.L2 U10.L3 U10.M6 U10.M15 U10.M16 U10.N2 U10.N3 U10.U1 U10.V1 USB1.A8 USB1.B8 USB2.A8 USB2.B8 USB3.A8 USB3.B8

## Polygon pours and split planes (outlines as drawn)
GND on Bottom Layer (solid, remove dead copper, pour order 1): 3362,3262.5 7158,3262.5 7158,5106.5 3362,5106.5
3V3 on Mid-Layer 1 (solid, remove dead copper, pour order 2): 3323,3202 7073,3202 7073,5136 3323,5136
GND on Top Layer (solid, remove dead copper, pour order 3): 3258.84,3116.18 7039.84,3116.18 7039.84,5210.18 3258.84,5210.18
GND on Mid-Layer 2 (solid, remove dead copper, pour order 6): 3208,3000 7206,3000 7206,5288 3208,5288
1V5 on Mid-Layer 1 (solid, remove dead copper): 5061,4684.5 5235.95,4856.47 5824.95,4856.47 5944.95,4736.47 5944.95,4428.47 5628.95,4112.47 5240.95,4112.47 5062.95,4290.47
0V9 on Mid-Layer 2 (solid, remove dead copper, pour order 4): 6135,4641.5 5991,4497.5 5991,4430.71 5662.97,4102.68 5419.86,4102.68 5353.47,4036.3 5353.47,3940.73 5382.35,3911.85 5539.69,3911.85 5876.42,3911.85 6196,4231.43 6196,4481.5 6245,4530.5 6245,4614.5 6218,4641.5
GND on Mid-Layer 2 (solid, remove dead copper, pour order 5): 5235.95,4856.47 5063,4683.52 5063,4403.5 5292,4174.5 5693,4174.5 5833,4314.5 5833,4667.5 5833,4729.5 5706,4856.5 5235.98,4856.5

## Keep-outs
Top Layer:
  region: 5230,4818.5 5671.41,4818.5 5797,4692.91 5797,4337.5 5728.48,4268.98 5198.9,4268.98 5192,4275.89 5192,4331.5 5137,4386.05 5137,4725.5
Bottom Layer:
  region: 5215.39,4819.08 5683.67,4819.08 5798.25,4704.5 5798.25,4339.08 5728.74,4269.57 5202.1,4269.57 5141,4332.53 5141,4745.5
Multi-Layer:
  region: 4542.16,3317.2 4910.16,3317.2 4910.16,3459.2 4542.16,3459.2

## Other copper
Top Layer:
  drawing of 1454 lines, arcs and shapes, not listed
Mid-Layer 1:
  pour cut-out net SCKP: 5436.56,4641.48 5426.77,4644.71 5423.94,4641.88 5427.17,4632.09
  pour cut-out net SCKP: 5436.56,4641.48 5426.77,4644.71 5423.94,4641.88 5427.17,4632.09
  pour cut-out net SCKN: 5416.55,4630.9 5418.12,4639.04 5415.29,4641.87 5407.15,4640.3
  pour cut-out net SCKN: 5416.55,4630.9 5407.15,4640.3 5406.29,4632.87 5409.12,4630.04
  pour cut-out net $2N3534: 5297.17,4200.5 5304.48,4208.32 5301.95,4217.11 5293.49,4213.26
  pour cut-out net $2N3534: 5297.17,4200.5 5304.48,4208.32 5301.95,4217.11 5293.49,4213.26
  pour cut-out net SCKP: 5743.22,4799.09 5733.27,4796.06 5742.12,4792.87 5740.69,4786.06
  pour cut-out net SCKP: 5743.22,4799.09 5735.12,4799.87 5733.27,4796.06 5740.69,4786.06
  pour cut-out net SCKN: 5739.83,4821.49 5733.89,4811.47 5735.49,4807.41 5744.68,4809.14
  pour cut-out net SCKN: 5739.83,4821.49 5733.89,4811.47 5735.49,4807.41 5744.68,4809.14
  pour cut-out net LDOA_OUT: 5358.08,4127.72 5368.73,4127 5374.89,4136 5365.58,4138.67
  pour cut-out net LDOA_OUT: 5358.08,4127.72 5368.73,4127 5374.89,4136 5365.58,4138.67
  pour cut-out net LDOA_OUT: 5348.17,4137.05 5342.82,4129.4 5349.9,4122.33 5357.55,4127.67
  pour cut-out net LDOA_OUT: 5348.17,4137.05 5342.82,4129.4 5349.9,4122.33 5357.55,4127.67
  pour cut-out net $2N3534: 5157.44,4275.67 5165.81,4271.03 5171.47,4276.69 5166.83,4285.05
  pour cut-out net $2N3534: 5157.44,4275.67 5165.81,4271.03 5171.47,4276.69 5166.83,4285.05
  pour cut-out net FEL: 5300.83,3771.95 5291.44,3781.33 5289.88,3774.62 5294.12,3770.38
  pour cut-out net FEL: 5300.83,3771.95 5303.12,3779.38 5298.88,3783.62 5291.44,3781.33
  pour cut-out net LDOA_OUT: 5546.55,4086.33 5538.54,4091.32 5532.18,4084.96 5537.17,4076.95
  pour cut-out net LDOA_OUT: 5546.55,4086.33 5538.54,4091.32 5532.18,4084.96 5537.17,4076.95
  pour cut-out net LDOA_OUT: 5296.44,4078.43 5296.44,4065.15 5302.29,4066.79 5302.29,4076.79
  pour cut-out net LDOA_OUT: 5296.44,4078.43 5287.29,4076.79 5287.29,4066.79 5296.44,4065.15
  pour cut-out net LDOA_OUT: 5308.14,4065.15 5317.34,4066.79 5317.34,4076.79 5308.14,4078.43
  pour cut-out net LDOA_OUT: 5308.14,4065.15 5317.34,4066.79 5317.34,4076.79 5308.14,4078.43
  pour cut-out net $7N19855: 4290.14,3399.14 4280.95,3395.5 4280.95,3389.5 4290.14,3385.86
  pour cut-out net $7N19855: 4290.14,3399.14 4280.95,3395.5 4280.95,3389.5 4290.14,3385.86
  pour cut-out net D0-: 5544.7,3863.67 5554.48,3860.45 5557.31,3863.28 5554.09,3873.05
  pour cut-out net D0-: 5544.7,3863.67 5554.48,3860.45 5557.31,3863.28 5554.09,3873.05
  pour cut-out net D0+: 5540.36,3839.31 5553.64,3839.31 5549,3845.17 5545,3845.17
  pour cut-out net D0+: 5540.36,3839.31 5545,3834.5 5549,3834.5 5553.64,3839.31
  pour cut-out net D1-: 5520.52,3836.67 5530.3,3833.45 5533.13,3836.28 5529.91,3846.05
  pour cut-out net D1-: 5520.52,3836.67 5530.3,3833.45 5533.13,3836.28 5529.91,3846.05
  pour cut-out net D1+: 5520.44,3809.67 5530.22,3806.45 5533.05,3809.28 5529.83,3819.05
  pour cut-out net D1+: 5520.44,3809.67 5530.22,3806.45 5533.05,3809.28 5529.83,3819.05
  pour cut-out net GND: 5666.15,3932.14 5656.95,3930.5 5656.95,3920.5 5666.15,3918.86
  pour cut-out net GND: 5666.15,3932.14 5656.95,3930.5 5656.95,3920.5 5666.15,3918.86
  pour cut-out net GND: 5628.93,3878.07 5627,3887.1 5617,3885.96 5615.74,3876.57
  pour cut-out net GND: 5628.93,3878.07 5627,3887.1 5617,3885.96 5615.74,3876.57
  pour cut-out net FEL: 6358.17,4429.05 6354.24,4419.98 6358.48,4415.74 6367.55,4419.67
  pour cut-out net FEL: 6358.17,4429.05 6354.24,4419.98 6358.48,4415.74 6367.55,4419.67
  pour cut-out net RESET: 5706.83,4077.95 5710.76,4087.02 5706.52,4091.26 5697.44,4087.33
  pour cut-out net RESET: 5706.83,4077.95 5710.76,4087.02 5706.52,4091.26 5697.44,4087.33
  pour cut-out net RESET: 5968.17,4398.05 5964.24,4388.98 5968.48,4384.74 5977.55,4388.67
  pour cut-out net RESET: 5968.17,4398.05 5964.24,4388.98 5968.48,4384.74 5977.55,4388.67
  pour cut-out net PE4: 5878.36,4257.65 5883,4248.45 5887,4248.45 5891.64,4257.65
  pour cut-out net PE4: 5878.36,4257.65 5883,4248.45 5887,4248.45 5891.64,4257.65
  pour cut-out net PE5: 5849.36,4253.65 5862.64,4253.65 5858,4259.5 5854,4259.5
  pour cut-out net PE5: 5849.36,4253.65 5854,4248.5 5858,4248.5 5862.64,4253.65
  pour cut-out net PE6: 5838.85,4237.86 5838.85,4251.14 5833,4246.5 5833,4242.5
  pour cut-out net PE6: 5838.85,4237.86 5847,4242.5 5847,4246.5 5838.85,4251.14
  pour cut-out net PE7: 5827.85,4213.86 5837.04,4218.5 5837.04,4222.5 5827.85,4227.14
  pour cut-out net PE7: 5827.85,4213.86 5837.04,4218.5 5837.04,4222.5 5827.85,4227.14
  pour cut-out net PE9: 5825.85,4187.86 5835.04,4192.5 5835.04,4196.5 5825.85,4201.14
  pour cut-out net PE9: 5825.85,4187.86 5835.04,4192.5 5835.04,4196.5 5825.85,4201.14
  pour cut-out net PE10: 5803.85,4170.86 5813.04,4175.5 5813.04,4179.5 5803.85,4184.14
  pour cut-out net PE10: 5803.85,4170.86 5813.04,4175.5 5813.04,4179.5 5803.85,4184.14
  pour cut-out net PE11: 5806.85,4143.86 5816.04,4148.5 5816.04,4152.5 5806.85,4157.14
  pour cut-out net PE11: 5806.85,4143.86 5816.04,4148.5 5816.04,4152.5 5806.85,4157.14
  pour cut-out net PE14: 5851.83,4131.95 5842.44,4141.33 5841.58,4133.91 5844.41,4131.09
  pour cut-out net PE14: 5851.83,4131.95 5853.41,4140.09 5850.58,4142.91 5842.44,4141.33
  pour cut-out net PE8: 5926.44,4243.67 5936.22,4240.45 5939.05,4243.28 5935.83,4253.05
  pour cut-out net PE8: 5926.44,4243.67 5936.22,4240.45 5939.05,4243.28 5935.83,4253.05
  pour cut-out net PE13: 5947.36,4246.65 5952,4237.45 5956,4237.45 5960.64,4246.65
  pour cut-out net PE13: 5947.36,4246.65 5952,4237.45 5956,4237.45 5960.64,4246.65
  pour cut-out net PE12: 5973.17,4254.05 5969.95,4244.28 5972.77,4241.45 5982.55,4244.67
  pour cut-out net PE12: 5973.17,4254.05 5969.95,4244.28 5972.77,4241.45 5982.55,4244.67
  pour cut-out net PE15: 6008.15,4252.14 5998.95,4247.5 5998.95,4243.5 6008.15,4238.86
  pour cut-out net PE15: 6008.15,4252.14 5998.95,4247.5 5998.95,4243.5 6008.15,4238.86
  pour cut-out net PE16: 5988.36,4202.65 5993,4193.45 5997,4193.45 6001.64,4202.65
  pour cut-out net PE16: 5988.36,4202.65 5993,4193.45 5997,4193.45 6001.64,4202.65
  pour cut-out net VBUS: 3717.17,4813.05 3711.82,4805.4 3718.9,4798.33 3726.55,4803.67
  pour cut-out net VBUS: 3717.17,4813.05 3711.82,4805.4 3718.9,4798.33 3726.55,4803.67
  pour cut-out net PE14: 5823.83,3666.95 5827.05,3676.72 5824.22,3679.55 5814.44,3676.33
  pour cut-out net PE14: 5823.83,3666.95 5827.05,3676.72 5824.22,3679.55 5814.44,3676.33
  pour cut-out net PE10: 5921.83,3671.95 5912.44,3681.33 5911.58,3673.91 5914.41,3671.09
  pour cut-out net PE10: 5921.83,3671.95 5923.41,3680.09 5920.58,3682.91 5912.44,3681.33
  pour cut-out net PE11: 5818.64,3475.35 5814,3484.55 5810,3484.55 5805.36,3475.35
  pour cut-out net PE11: 5818.64,3475.35 5814,3484.55 5810,3484.55 5805.36,3475.35
  pour cut-out net PE9: 5916.64,3495.35 5912,3504.55 5908,3504.55 5903.36,3495.35
  pour cut-out net PE9: 5916.64,3495.35 5912,3504.55 5908,3504.55 5903.36,3495.35
  pour cut-out net PE6: 6019.83,3467.95 6020.41,3475.09 6017.58,3477.91 6010.44,3477.33
  pour cut-out net PE6: 6019.83,3467.95 6010.44,3477.33 6009.58,3469.91 6012.41,3467.09
  pour cut-out net PE7: 6007.76,3678.24 6011.41,3688.09 6008.58,3690.91 5999.15,3688.35
  pour cut-out net PE7: 6007.76,3678.24 5999.15,3688.35 5998.58,3680.91 6001.41,3678.09
  pour cut-out net PE5: 6113.64,3462.35 6109,3471.55 6105,3471.55 6100.36,3462.35
  pour cut-out net PE5: 6113.64,3462.35 6109,3471.55 6105,3471.55 6100.36,3462.35
  pour cut-out net PE4: 6214.55,3471.33 6204.77,3474.55 6201.95,3471.72 6205.17,3461.95
  pour cut-out net PE4: 6214.55,3471.33 6204.77,3474.55 6201.95,3471.72 6205.17,3461.95
  pour cut-out net PE8: 6311.55,3471.33 6301.77,3474.55 6298.95,3471.72 6302.17,3461.95
  pour cut-out net PE8: 6311.55,3471.33 6301.77,3474.55 6298.95,3471.72 6302.17,3461.95
  pour cut-out net PE13: 6414.55,3474.33 6404.77,3477.55 6401.95,3474.72 6405.17,3464.95
  pour cut-out net PE13: 6414.55,3474.33 6404.77,3477.55 6401.95,3474.72 6405.17,3464.95
  pour cut-out net PE12: 6307.36,3655.65 6312,3646.45 6316,3646.45 6320.64,3655.65
  pour cut-out net PE12: 6307.36,3655.65 6312,3646.45 6316,3646.45 6320.64,3655.65
  pour cut-out net PE15: 6204.36,3652.65 6209,3643.45 6213,3643.45 6217.64,3652.65
  pour cut-out net PE15: 6204.36,3652.65 6209,3643.45 6213,3643.45 6217.64,3652.65
  pour cut-out net PE16: 6110.55,3678.33 6100.77,3681.55 6097.95,3678.72 6101.17,3668.95
  pour cut-out net PE16: 6110.55,3678.33 6100.77,3681.55 6097.95,3678.72 6101.17,3668.95
  pour cut-out net D1+: 5764.55,3786.33 5754.77,3789.55 5751.95,3786.72 5755.17,3776.95
  pour cut-out net D1+: 5764.55,3786.33 5754.77,3789.55 5751.95,3786.72 5755.17,3776.95
  pour cut-out net D1-: 5791.13,3786.31 5781.57,3788.76 5779.2,3785.47 5783.37,3775.54
  pour cut-out net D1-: 5791.13,3786.31 5781.57,3788.76 5779.2,3785.47 5783.37,3775.54
  pour cut-out net D0+: 5832.83,3760.95 5835.41,3770.09 5832.58,3772.91 5823.44,3770.33
  pour cut-out net D0+: 5832.83,3760.95 5823.44,3770.33 5822.58,3762.91 5825.41,3760.09
  pour cut-out net D0-: 5853.55,3771.33 5845.41,3772.91 5842.58,3770.09 5844.17,3761.95
  pour cut-out net D0-: 5853.55,3771.33 5844.17,3761.95 5851.58,3761.09 5854.41,3763.91
  pour cut-out net AP_CLK_OUT: 5701.17,4014.05 5710.55,4004.67 5712.83,4010.67 5707.17,4016.33
  pour cut-out net AP_CLK_OUT: 5701.17,4014.05 5698.17,4007.33 5703.83,4001.67 5710.55,4004.67
  pour cut-out net AP_CLK_OUT: 5146.07,3421.24 5155.57,3423.5 5156.48,3431.5 5147.57,3434.43
  pour cut-out net AP_CLK_OUT: 5146.07,3421.24 5155.57,3423.5 5156.48,3431.5 5147.57,3434.43
  pour cut-out net LDOA_OUT: 5131.44,4079.67 5139.1,4074.33 5146.17,4081.4 5140.83,4089.05
  pour cut-out net LDOA_OUT: 5131.44,4079.67 5139.1,4074.33 5146.17,4081.4 5140.83,4089.05
  pour cut-out net VBUS: 3704.83,3841.95 3710.17,3849.6 3703.1,3856.67 3695.44,3851.33
  pour cut-out net VBUS: 3704.83,3841.95 3710.17,3849.6 3703.1,3856.67 3695.44,3851.33
  pour cut-out net $7N19855: 3695.44,3618.67 3704.52,3614.74 3708.76,3618.98 3704.83,3628.05
  pour cut-out net $7N19855: 3695.44,3618.67 3704.52,3614.74 3708.76,3618.98 3704.83,3628.05
  pour cut-out net LCD_D7: 4644.44,4155.15 4639.8,4164.35 4635.8,4164.35 4631.16,4155.15
  pour cut-out net LCD_D7: 4644.44,4155.15 4639.8,4164.35 4635.8,4164.35 4631.16,4155.15
  pour cut-out net LCD_RST: 5020.15,4282.14 5010.95,4277.5 5010.95,4273.5 5020.15,4268.86
  pour cut-out net LCD_RST: 5020.15,4282.14 5010.95,4277.5 5010.95,4273.5 5020.15,4268.86
  pour cut-out net LCD_D7: 5034.15,4402.14 5024.95,4397.5 5024.95,4393.5 5034.15,4388.86
  pour cut-out net LCD_D7: 5034.15,4402.14 5024.95,4397.5 5024.95,4393.5 5034.15,4388.86
  pour cut-out net LCD_RST: 4636.64,3872.35 4632,3881.55 4628,3881.55 4623.36,3872.35
  pour cut-out net LCD_RST: 4636.64,3872.35 4632,3881.55 4628,3881.55 4623.36,3872.35
Mid-Layer 2:
  pour cut-out net SVREF: 5295.56,4224.41 5304.76,4224.56 5304.76,4237.56 5295.56,4237.7
  pour cut-out net SVREF: 5295.56,4224.41 5304.76,4224.56 5304.76,4237.56 5295.56,4237.7
  pour cut-out net SVREF: 5185.54,4303.9 5191.94,4310.5 5182.75,4319.69 5176.15,4313.29
  pour cut-out net SVREF: 5185.54,4303.9 5191.94,4310.5 5182.75,4319.69 5176.15,4313.29
  pour cut-out net LCD_HS: 5232.36,4275.65 5237,4266.45 5241,4266.45 5245.64,4275.65
  pour cut-out net LCD_HS: 5232.36,4275.65 5237,4266.45 5241,4266.45 5245.64,4275.65
  pour cut-out net LCD_VS: 5255.17,4257.05 5251.95,4247.28 5254.77,4244.45 5264.55,4247.67
  pour cut-out net LCD_VS: 5255.17,4257.05 5251.95,4247.28 5254.77,4244.45 5264.55,4247.67
  pour cut-out net UART1_RX: 5566.55,3508.33 5558.41,3509.91 5555.58,3507.09 5557.17,3498.95
  pour cut-out net UART1_RX: 5566.55,3508.33 5557.17,3498.95 5564.58,3498.09 5567.41,3500.91
  pour cut-out net UART1_TX: 5583.64,3532.35 5579,3541.55 5575,3541.55 5570.36,3532.35
  pour cut-out net UART1_TX: 5583.64,3532.35 5579,3541.55 5575,3541.55 5570.36,3532.35
  pour cut-out net UART1_RTS: 5609.55,3534.33 5599.77,3537.55 5596.95,3534.72 5600.17,3524.95
  pour cut-out net UART1_RTS: 5609.55,3534.33 5599.77,3537.55 5596.95,3534.72 5600.17,3524.95
  pour cut-out net UART1_CTS: 5628.83,3499.95 5619.44,3509.33 5618.58,3501.91 5621.41,3499.09
  pour cut-out net UART1_CTS: 5628.83,3499.95 5628.41,3506.09 5625.58,3508.91 5619.44,3509.33
  pour cut-out net UART1_RX: 5544.44,3663.67 5554.22,3660.45 5557.05,3663.28 5553.83,3673.05
  pour cut-out net UART1_RX: 5544.44,3663.67 5554.22,3660.45 5557.05,3663.28 5553.83,3673.05
  pour cut-out net UART1_TX: 5542.44,3690.67 5552.22,3687.45 5555.05,3690.28 5551.83,3700.05
  pour cut-out net UART1_TX: 5542.44,3690.67 5552.22,3687.45 5555.05,3690.28 5551.83,3700.05
  pour cut-out net UART1_CTS: 5562.6,3715.49 5572.6,3708.07 5577.34,3708.99 5575.63,3718.02
  pour cut-out net UART1_CTS: 5562.6,3715.49 5572.6,3708.07 5577.34,3708.99 5575.63,3718.02
  pour cut-out net UART1_RTS: 5558.56,3753.57 5550.25,3743.58 5550.73,3738.4 5559.78,3740.35
  pour cut-out net UART1_RTS: 5558.56,3753.57 5550.25,3743.58 5550.73,3738.4 5559.78,3740.35
  pour cut-out net 3V3: 5634.42,3972.64 5643.8,3982.03 5637.8,3984.3 5632.14,3978.64
  pour cut-out net 3V3: 5634.42,3972.64 5641.17,3969.62 5646.83,3975.27 5643.8,3982.03
  pour cut-out net 3V3: 5309.36,4174.65 5311,4165.45 5321,4165.45 5322.64,4174.65
  pour cut-out net 3V3: 5309.36,4174.65 5311,4165.45 5321,4165.45 5322.64,4174.65
  pour cut-out net 3V3: 5366.55,4085.33 5358.9,4090.67 5351.82,4083.6 5357.17,4075.95
  pour cut-out net 3V3: 5366.55,4085.33 5358.9,4090.67 5351.82,4083.6 5357.17,4075.95
  pour cut-out net BT_WAKE_AP: 5622.55,3570.33 5612.77,3573.55 5609.95,3570.72 5613.17,3560.95
  pour cut-out net BT_WAKE_AP: 5622.55,3570.33 5612.77,3573.55 5609.95,3570.72 5613.17,3560.95
  pour cut-out net AP_WAKE_BT: 5630.55,3600.33 5621.17,3590.95 5628.58,3590.09 5631.41,3592.91
  pour cut-out net AP_WAKE_BT: 5630.55,3600.33 5623.41,3600.91 5620.58,3598.09 5621.17,3590.95
  pour cut-out net BT_WAKE_AP: 5588.11,3902.54 5582.19,3892.52 5583.8,3888.47 5593,3890.2
  pour cut-out net BT_WAKE_AP: 5588.11,3902.54 5582.19,3892.52 5583.8,3888.47 5593,3890.2
  pour cut-out net AP_WAKE_BT: 5596.44,3863.93 5606.22,3860.71 5609.05,3863.54 5605.83,3873.32
  pour cut-out net AP_WAKE_BT: 5596.44,3863.93 5606.22,3860.71 5609.05,3863.54 5605.83,3873.32
  pour cut-out net LCD_PWM: 4077,4839.56 4084,4827.1 4088,4827.1 4095,4839.56
  pour cut-out net 3V3: 5307.36,3967.65 5309,3958.45 5319,3958.45 5320.64,3967.65
  pour cut-out net 3V3: 5307.36,3967.65 5309,3958.45 5319,3958.45 5320.64,3967.65
  pour cut-out net 3V3: 5412.15,3904.14 5402.95,3902.5 5402.95,3892.5 5412.15,3890.86
  pour cut-out net 3V3: 5412.15,3904.14 5402.95,3902.5 5402.95,3892.5 5412.15,3890.86
  pour cut-out net PE12: 5583.07,4141.24 5592.8,4145.5 5593.25,4149.5 5584.57,4154.43
  pour cut-out net PE12: 5583.07,4141.24 5592.8,4145.5 5593.25,4149.5 5584.57,4154.43
  pour cut-out net PE16: 5571.44,4118.42 5581.22,4115.2 5584.05,4118.03 5580.83,4127.81
  pour cut-out net PE16: 5571.44,4118.42 5581.22,4115.2 5584.05,4118.03 5580.83,4127.81
  pour cut-out net PE13: 5625.83,4145.95 5629.05,4155.72 5626.22,4158.55 5616.44,4155.33
  pour cut-out net PE13: 5625.83,4145.95 5629.05,4155.72 5626.22,4158.55 5616.44,4155.33
  pour cut-out net PE8: 5648.83,4142.95 5639.44,4152.33 5638.58,4144.91 5641.41,4142.09
  pour cut-out net PE8: 5648.83,4142.95 5648.41,4149.09 5645.58,4151.91 5639.44,4152.33
  pour cut-out net PE8: 5933.64,4258.35 5929,4267.55 5925,4267.55 5920.36,4258.35
  pour cut-out net PE8: 5933.64,4258.35 5929,4267.55 5925,4267.55 5920.36,4258.35
  pour cut-out net PE13: 5960.64,4258.35 5947.36,4258.35 5952,4252.5 5956,4252.5
  pour cut-out net PE13: 5960.64,4258.35 5956,4263.5 5952,4263.5 5947.36,4258.35
  pour cut-out net PE12: 5982.55,4262.33 5972.77,4265.55 5969.95,4262.72 5973.17,4252.95
  pour cut-out net PE12: 5982.55,4262.33 5972.77,4265.55 5969.95,4262.72 5973.17,4252.95
  pour cut-out net PE15: 6005.17,4246.05 6001.95,4236.28 6004.77,4233.45 6014.55,4236.67
  pour cut-out net PE15: 6005.17,4246.05 6001.95,4236.28 6004.77,4233.45 6014.55,4236.67
  pour cut-out net PE16: 5995.55,4217.33 5988.41,4217.91 5985.58,4215.09 5986.17,4207.95
  pour cut-out net PE16: 5995.55,4217.33 5986.17,4207.95 5993.58,4207.09 5996.41,4209.91
  pour cut-out net UART0_RX: 5876.55,4439.33 5867.17,4429.95 5874.58,4429.09 5877.41,4431.91
  pour cut-out net UART0_RX: 5876.55,4439.33 5868.41,4440.91 5865.58,4438.09 5867.17,4429.95
  pour cut-out net UART0_TX: 5857.83,4429.95 5848.44,4439.33 5847.58,4431.91 5850.41,4429.09
  pour cut-out net UART0_TX: 5857.83,4429.95 5858.41,4437.09 5855.58,4439.91 5848.44,4439.33
  pour cut-out net 3V3: 5745.26,3829.26 5742,3837.85 5734,3834.97 5732.77,3824.76
  pour cut-out net 3V3: 5745.26,3829.26 5742,3837.85 5734,3834.97 5732.77,3824.76
  pour cut-out net LDOA_OUT: 5125.07,4179.93 5127,4170.9 5137,4172.04 5138.26,4181.43
  pour cut-out net LDOA_OUT: 5125.07,4179.93 5127,4170.9 5137,4172.04 5138.26,4181.43
  pour cut-out net LDOA_OUT: 5138.64,4094.35 5137,4103.55 5127,4103.55 5125.36,4094.35
  pour cut-out net LDOA_OUT: 5138.64,4094.35 5137,4103.55 5127,4103.55 5125.36,4094.35
  pour cut-out net UART0_RX: 5032.15,4557.14 5023,4552.5 5023,4548.5 5032.15,4543.86
  pour cut-out net UART0_RX: 5032.15,4557.14 5032.15,4543.86 5038,4548.5 5038,4552.5
  pour cut-out net UART0_TX: 5031.43,4581.43 5022.74,4576.5 5023.2,4572.5 5032.93,4568.24
  pour cut-out net UART0_TX: 5031.43,4581.43 5022.74,4576.5 5023.2,4572.5 5032.93,4568.24
  pour cut-out net LCD_VS: 4758.64,4068.35 4754,4077.55 4750,4077.55 4745.36,4068.35
  pour cut-out net LCD_VS: 4758.64,4068.35 4754,4077.55 4750,4077.55 4745.36,4068.35
  pour cut-out net LCD_HS: 4723.83,4054.95 4727.05,4064.72 4724.22,4067.55 4714.44,4064.33
  pour cut-out net LCD_HS: 4723.83,4054.95 4727.05,4064.72 4724.22,4067.55 4714.44,4064.33
  pour cut-out net LCD_PWM: 5340.44,4042.67 5350.22,4039.45 5353.05,4042.28 5349.83,4052.05
  pour cut-out net LCD_PWM: 5340.44,4042.67 5350.22,4039.45 5353.05,4042.28 5349.83,4052.05
Bottom Layer:
  drawing of 366 lines, arcs and shapes, not listed

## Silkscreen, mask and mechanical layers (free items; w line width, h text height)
Top Overlay:
  text "装不回去了吧" at 5224.78,4644.22 h90.62
  text "DEBUG" at 3622.53,4624.6 h32.45
  text "DRAM" at 5581.8,4478.6 h32.45
  text "Allwinner D1-H" at 5181.55,4329.6 h32.45
  text "CPU" at 5642.23,4329.6 h32.45
  text "YuzukiRuler" at 3601,3988.5 h180
  text "LICENSE UNDER" at 3770.57,3946.82 h38.94
  text "CERN-OHL-P" at 3774.7,3899.82 h38.94
  text "Pro" at 3613,3878.5 h120
  text "TF Card" at 6463.68,3871.6 h32.45
  text "eMMC" at 5880.9,3789.3 h32.45 r90
  text "HDMI" at 3649.95,3644.6 h32.45
  text "JLCJLCJLCJLCJLCJLCJLCJLC" at 5755.06,3551.6 h32.45
Mechanical 1:
  lines w1: 3450,3546 3524,3546 3524,4777 3450,4777 3450,3546
  lines w10: 3404,3382.37 3404,4933.55 cw(c3474.87,4933.55) 3474.87,5004.41 6876.44,5004.41 cw(c6876.44,4933.55) 6947.31,4933.55 6947.31,3382.37 cw(c6876.44,3382.37) 6876.44,3311.5 3474.87,3311.5 cw(c3474.87,3382.37) 3404,3382.37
